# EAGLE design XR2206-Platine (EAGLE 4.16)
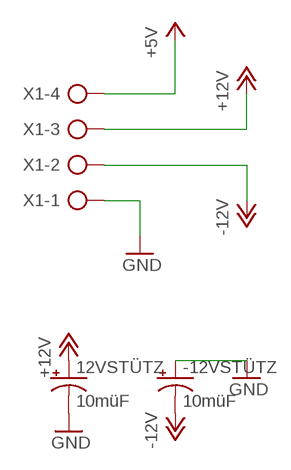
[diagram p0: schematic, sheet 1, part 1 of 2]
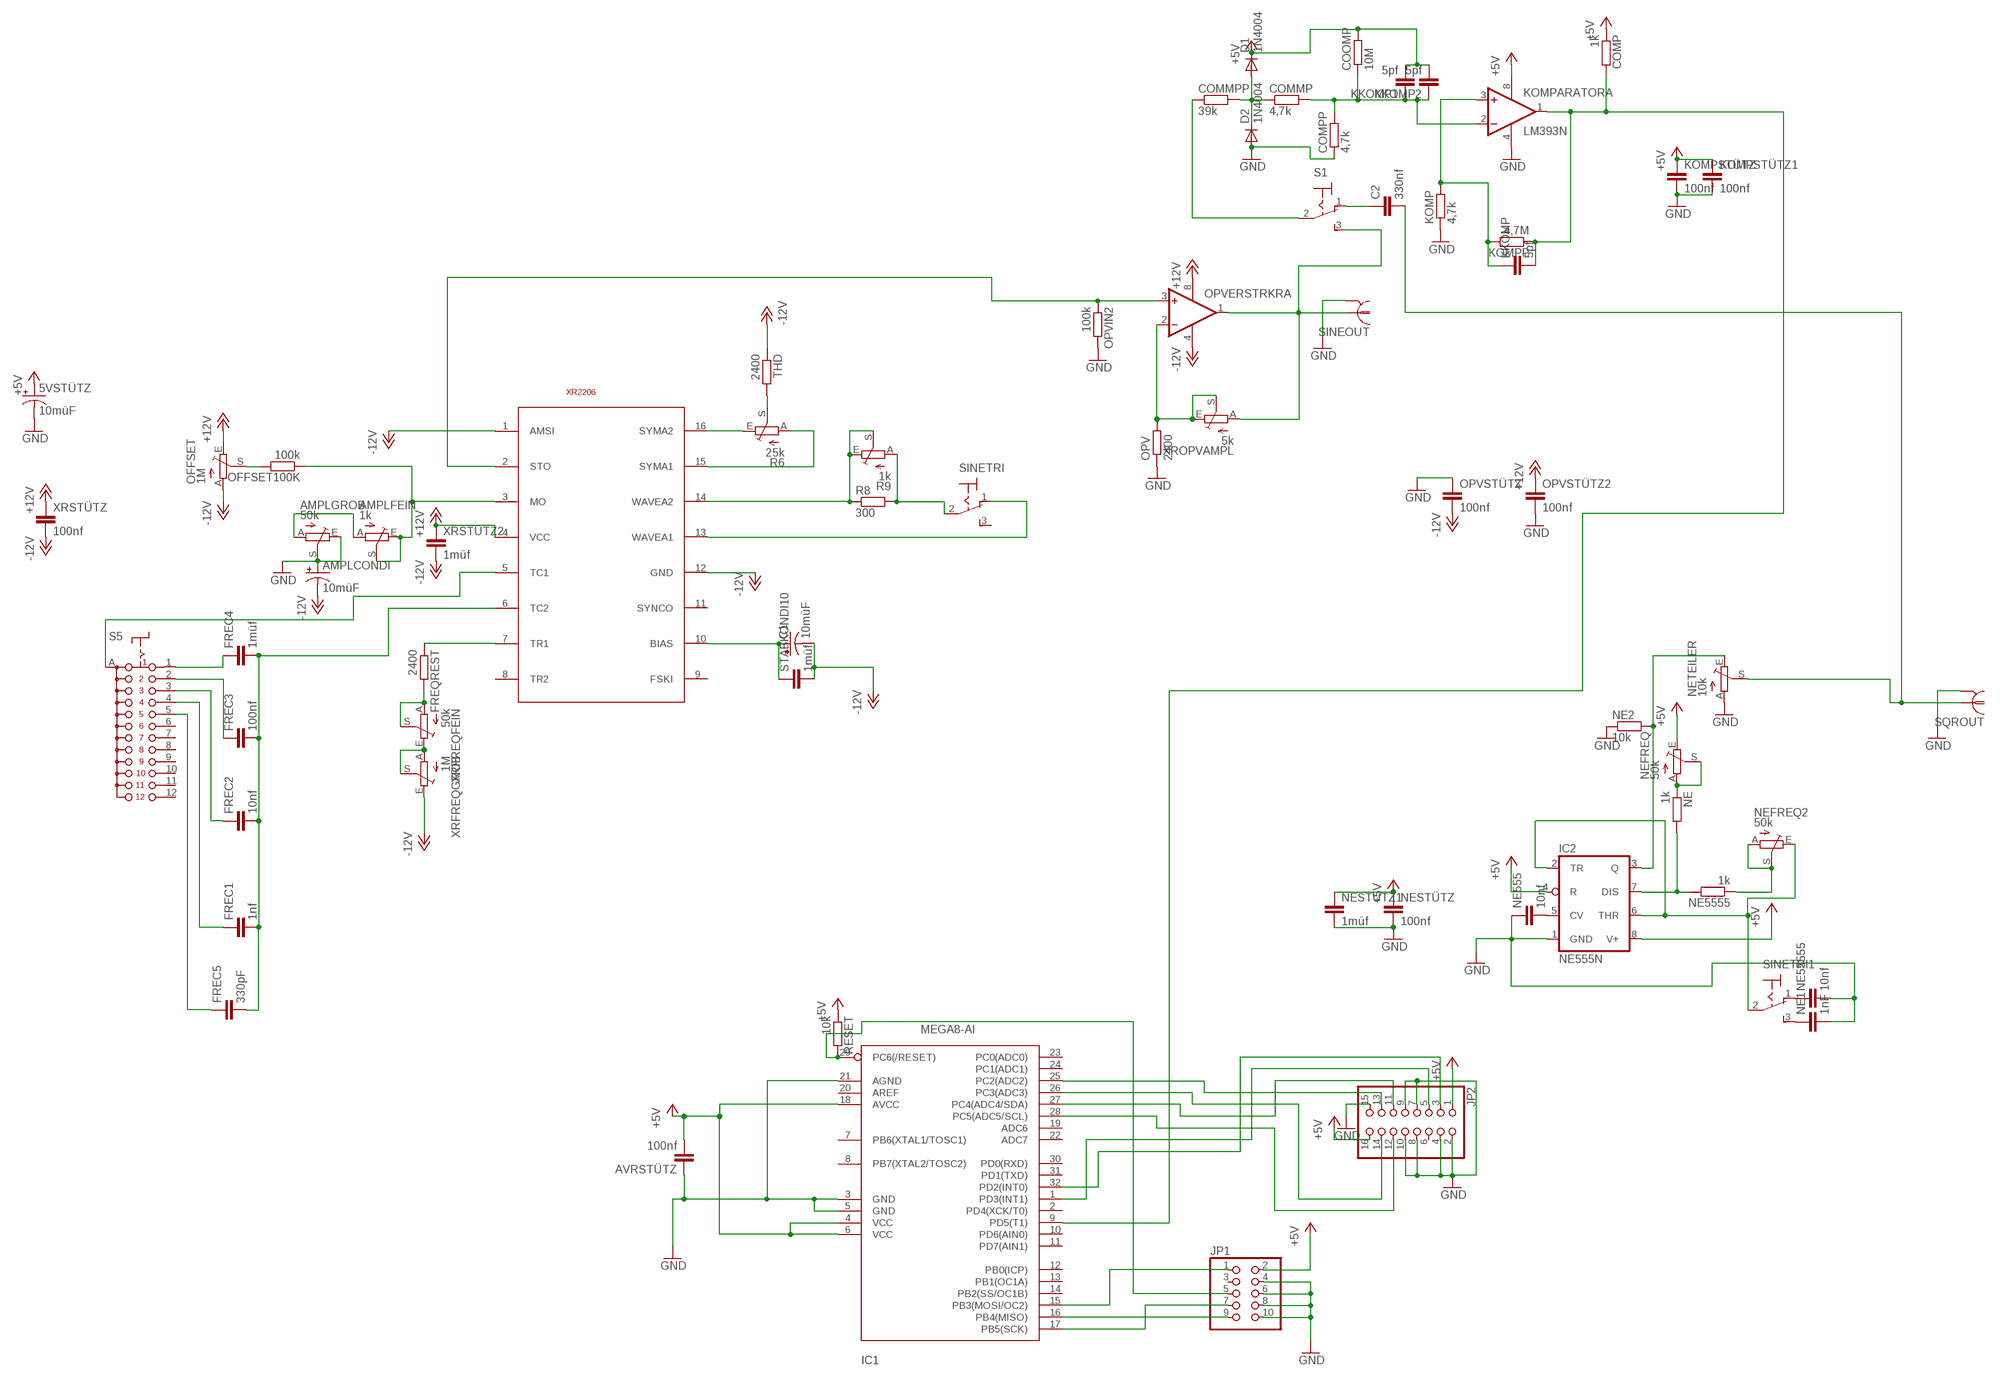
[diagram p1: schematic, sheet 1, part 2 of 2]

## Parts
5VSTÜTZ  10müF  CPOL-USE2.5-5  [E2,5-5]
12VSTÜTZ  10müF  CPOL-USE2.5-5  [E2,5-5]
-12VSTÜTZ  10müF  CPOL-USE2.5-5  [E2,5-5]
AMPLCONDI  10müF  CPOL-USE2.5-5  [E2,5-5]
AMPLFEIN  1k  TRIM_EU-LI10  [LI10]
AMPLGROB  50k  TRIM_EU-LI10  [LI10]
AVRSTÜTZ  100nf  C-EUC0603  [C0603]
C1  10müF  CPOL-USE2.5-5  [E2,5-5]
C2  330nf  C-EU050-025X075  [C050-025X075]
COMMP  4,7k  R-EU_R0603  [R0603]
COMMPP  39k  R-EU_R0603  [R0603]
COMP  1k  R-EU_R0603  [R0603]
COMPP  4,7k  R-EU_R0603  [R0603]
COOMP  10M  R-EU_R0603  [R0603]
D1  1N4004  [DO41-10]
D2  1N4004  [DO41-10]
FREC1  1nf  C-EUC0603  [C0603]
FREC2  10nf  C-EUC0603  [C0603]
FREC3  100nf  C-EUC0603  [C0603]
FREC4  1müf  C-EUC0603  [C0603]
FREC5  330pF  C-EUC0603  [C0603]
FREQREST  2400  R-EU_R0603  [R0603]
IC1  MEGA8-AI  [TQFP32-08]
IC2  NE555N  [DIL08]
JP1  PINHD-2X5  [2X05]
JP2  PINHD-2X8  [2X08]
KKOMP  5pf  C-EUC0603  [C0603]
KKOMP1  5pf  C-EUC0603  [C0603]
KKOMP2  5pf  C-EUC0603  [C0603]
KOMP  4,7k  R-EU_R0603  [R0603]
KOMPARATOR  LM393N  [DIL08]
KOMPP  4,7M  R-EU_R0603  [R0603]
KOMPSTÜTZ  100nf  C-EUC0603  [C0603]
KOMPSTÜTZ1  100nf  C-EUC0603  [C0603]
NE  1k  R-EU_R0603  [R0603]
NE1  1nF  C-EUC0603  [C0603]
NE2  10k  R-EU_R0603  [R0603]
NE555  10nf  C-EUC0603  [C0603]
NE5555  1k  R-EU_R0603  [R0603]
NE55555  10nf  C-EUC0603  [C0603]
NEFREQ  50k  TRIM_EU-LI10  [LI10]
NEFREQ2  50k  TRIM_EU-LI10  [LI10]
NESTÜTZ  100nf  C-EUC0603  [C0603]
NESTÜTZ1  1müf  C-EUC0603  [C0603]
NETEILER  10k  TRIM_EU-LI10  [LI10]
OFFSET  1M  TRIM_EU-LI10  [LI10]
OFFSET100K  100k  R-EU_R0603  [R0603]
OPV  2400  R-EU_R0603  [R0603]
OPVERSTRKR  2AMP_P8+4N  [DIL08]
OPVIN2  100k  R-EU_R0603  [R0603]
OPVSTÜTZ  100nf  C-EUC0603  [C0603]
OPVSTÜTZ2  100nf  C-EUC0603  [C0603]
R6  25k  TRIM_EU-LI10  [LI10]
R8  300  R-EU_R0603  [R0603]
R9  1k  TRIM_EU-LI10  [LI10]
RESET  10k  R-EU_R0603  [R0603]
S1  320-916  [320-916]
S5  CK101X12  [CK101X12]
SINEOUT  R141426  [R141426]
SINETRI  320-916  [320-916]
SINETRI1  320-916  [320-916]
SQROUT  R141426  [R141426]
STABKONDI10  1müf  C-EUC0603  [C0603]
THD  2400  R-EU_R0603  [R0603]
U$1  XR2206  [DIL16]
X1  AK300/4  [AK300/4]
XRFREQFEIN  50k  TRIM_EU-LI10  [LI10]
XRFREQGROB  1M  TRIM_EU-LI10  [LI10]
XROPVAMPL  5k  TRIM_EU-LI10  [LI10]
XRSTÜTZ  100nf  C-EUC0603  [C0603]
XRSTÜTZ2  1müf  C-EUC0603  [C0603]

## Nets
+5V: 5VSTÜTZ.+ AVRSTÜTZ.2 COMP.1 COOMP.2 D1.C IC1.4(VCC) IC1.6(VCC) IC1.18(AVCC) IC2.4(R) IC2.8(V+) JP1.2 JP2.1 JP2.16 KKOMP1.2 KKOMP2.2 KOMPARATOR.8(P:V+) KOMPSTÜTZ1.1 KOMPSTÜTZ.1 NEFREQ.E NESTÜTZ1.1 NESTÜTZ.1 RESET.1 X1.4
+12V: 12VSTÜTZ.+ OFFSET.E OPVERSTRKR.8(P:V+) OPVSTÜTZ2.1 U$1.4(VCC) X1.3 XRSTÜTZ2.1 XRSTÜTZ.1
-12V: -12VSTÜTZ.- AMPLCONDI.- C1.- OFFSET.A OPVERSTRKR.4(P:V-) OPVSTÜTZ.2 STABKONDI10.2 THD.1 U$1.1(AMSI) U$1.12(GND) X1.2 XRFREQGROB.E XRSTÜTZ2.2 XRSTÜTZ.2
GND: 5VSTÜTZ.- 12VSTÜTZ.- -12VSTÜTZ.+ AMPLCONDI.+ AMPLGROB.E AMPLGROB.S AVRSTÜTZ.1 COMPP.1 D2.A IC1.3(GND) IC1.5(GND) IC1.21(AGND) IC2.1(GND) JP1.4 JP1.6 JP1.8 JP1.10 JP2.2 JP2.4 JP2.7 JP2.8 JP2.9 JP2.10 JP2.15 KOMP.1 KOMPARATOR.4(P:V-) KOMPSTÜTZ1.2 KOMPSTÜTZ.2 NE1.2 NE2.1 NE555.1 NE55555.2 NESTÜTZ1.2 NESTÜTZ.2 NETEILER.A OPV.1 OPVIN2.2 OPVSTÜTZ2.2 OPVSTÜTZ.1 SINEOUT.2(GND) SQROUT.2(GND) X1.1
N$1: IC1.17(PB5(SCK)) JP1.7
N$2: IC2.7(DIS) NE5555.2 NE.2
N$3: FREQREST.1 U$1.7(TR1)
N$4: OFFSET100K.2 OFFSET.S
N$5: NE.1 NEFREQ.A NEFREQ.S
N$6: SINETRI.1(O) U$1.13(WAVEA1)
N$7: R6.E U$1.16(SYMA2)
N$8: R6.A U$1.15(SYMA1)
N$9: R6.S THD.2
N$10: R8.1 R9.E R9.S U$1.14(WAVEA2)
N$11: IC2.5(CV) NE555.2
N$12: R8.2 R9.A SINETRI.2(P)
N$13: S5.A U$1.5(TC1)
N$14: FREC4.1 S5.1
N$15: FREC3.1 S5.2
N$16: FREC2.1 S5.3
N$17: FREC1.1 S5.4
N$18: FREC1.2 FREC2.2 FREC3.2 FREC4.2 FREC5.2 U$1.6(TC2)
N$19: C1.+ STABKONDI10.1 U$1.10(BIAS)
N$20: OPVERSTRKR.3(A:+IN) OPVIN2.1 U$1.2(STO)
N$21: IC1.16(PB4(MISO)) JP1.9
N$22: OPV.2 OPVERSTRKR.2(A:-IN) XROPVAMPL.E XROPVAMPL.S
N$23: OPVERSTRKR.1(A:OUT) S1.3(S) SINEOUT.1 XROPVAMPL.A
N$24: AMPLFEIN.E AMPLFEIN.S OFFSET100K.1 U$1.3(MO)
N$25: IC2.2(TR) IC2.6(THR) NEFREQ2.E SINETRI1.2(P)
N$26: IC2.3(Q) NE2.2 NETEILER.E
N$27: AMPLFEIN.A AMPLGROB.A
N$28: NE5555.1 NEFREQ2.A NEFREQ2.S
N$29: FREQREST.2 XRFREQFEIN.A XRFREQFEIN.S
N$30: C2.1 S1.1(O)
N$31: IC1.29(PC6(/RESET)) JP1.5 RESET.2
N$32: COMP.2 IC1.9(PD5(T1)) KKOMP.2 KOMPARATOR.1(A:OUT) KOMPP.1
N$33: COMMP.1 COMMPP.2 D1.A D2.C
N$34: COMMP.2 COMPP.2 COOMP.1 KKOMP1.1 KKOMP2.1 KOMPARATOR.2(A:-IN)
N$35: FREC5.1 S5.5
N$36: KKOMP.1 KOMP.2 KOMPARATOR.3(A:+IN) KOMPP.2
N$37: XRFREQFEIN.E XRFREQGROB.A XRFREQGROB.S
N$38: IC1.15(PB3(MOSI/OC2)) JP1.1
N$40: COMMPP.1 S1.2(P)
N$41: NE55555.1 SINETRI1.1(O)
N$42: NE1.1 SINETRI1.3(S)
N$43: IC1.32(PD2(INT0)) JP2.3
N$44: IC1.1(PD3(INT1)) JP2.5
N$45: IC1.28(PC5(ADC5/SCL)) JP2.12
N$46: IC1.27(PC4(ADC4/SDA)) JP2.11
N$47: IC1.26(PC3(ADC3)) JP2.14
N$49: IC1.25(PC2(ADC2)) JP2.13
NEKOMP: C2.2 NETEILER.S SQROUT.1
Unconnected: IC1.2(PD4(XCK/T0)) IC1.7(PB6(XTAL1/TOSC1)) IC1.8(PB7(XTAL2/TOSC2)) IC1.10(PD6(AIN0)) IC1.11(PD7(AIN1)) IC1.12(PB0(ICP)) IC1.13(PB1(OC1A)) IC1.14(PB2(SS/OC1B)) IC1.19(ADC6) IC1.20(AREF) IC1.22(ADC7) IC1.23(PC0(ADC0)) IC1.24(PC1(ADC1)) IC1.30(PD0(RXD)) IC1.31(PD1(TXD)) JP1.3 JP2.6 KOMPARATOR.5(B:+IN) KOMPARATOR.6(B:-IN) KOMPARATOR.7(B:OUT) OPVERSTRKR.5(B:+IN) OPVERSTRKR.6(B:-IN) OPVERSTRKR.7(B:OUT) S5.6 S5.7 S5.8 S5.9 S5.10 S5.11 S5.12 SINETRI.3(S) U$1.8(TR2) U$1.9(FSKI) U$1.11(SYNCO)

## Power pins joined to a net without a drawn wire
GND: SINEOUT.3(GND) SINEOUT.4(GND) SINEOUT.5(GND) SQROUT.3(GND) SQROUT.4(GND) SQROUT.5(GND)

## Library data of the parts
5VSTÜTZ 12VSTÜTZ -12VSTÜTZ AMPLCONDI C1 = rcl:CPOL-US: POLARIZED CAPACITOR, American symbol
AMPLFEIN AMPLGROB NEFREQ NEFREQ2 NETEILER OFFSET R6 R9 XRFREQFEIN XRFREQGROB XROPVAMPL = pot:TRIM_EU-: POTENTIOMETER
AVRSTÜTZ C2 FREC1-FREC5 KKOMP KKOMP1 KKOMP2 KOMPSTÜTZ KOMPSTÜTZ1 NE1 NE555 NE55555 NESTÜTZ NESTÜTZ1 OPVSTÜTZ OPVSTÜTZ2 STABKONDI10 XRSTÜTZ XRSTÜTZ2 = rcl:C-EU: CAPACITOR, European symbol
COMMP COMMPP COMP COMPP COOMP FREQREST KOMP KOMPP NE NE2 NE5555 OFFSET100K OPV OPVIN2 R8 RESET THD = rcl:R-EU_: RESISTOR, European symbol
D1 D2 = diode:1N4004: DIODE
IC1 = atmel:MEGA8: MICROCONTROLLER 8 Kbytes FLASH 1 kbytes SRAM 512 bytes EEPROM USART 6-channel 10 bit ADC 2-channel 8 bit ADC Source: avr.lbr
IC2 = linear:*555: TIMER
JP1 = pinhead:PINHD-2X5: PIN HEADER
JP2 = pinhead:PINHD-2X8: PIN HEADER
KOMPARATOR = linear:LM393: COMPARATOR
OPVERSTRKR = linear:2AMP_P8+4: OP AMP
S1 SINETRI SINETRI1 = switch:320-916: TOGGLE SWITCH distributor RS Components
S5 = switch:CK101X12: ROTARY SWITCH C&K
SINEOUT SQROUT = con-coax:R141426: BNC COAX CONNECTOR Radiall 50/75 Ohm Spoerle
U$1 = linear:XR2206
X1 = con-ptr500:AK300/4: CONNECTOR

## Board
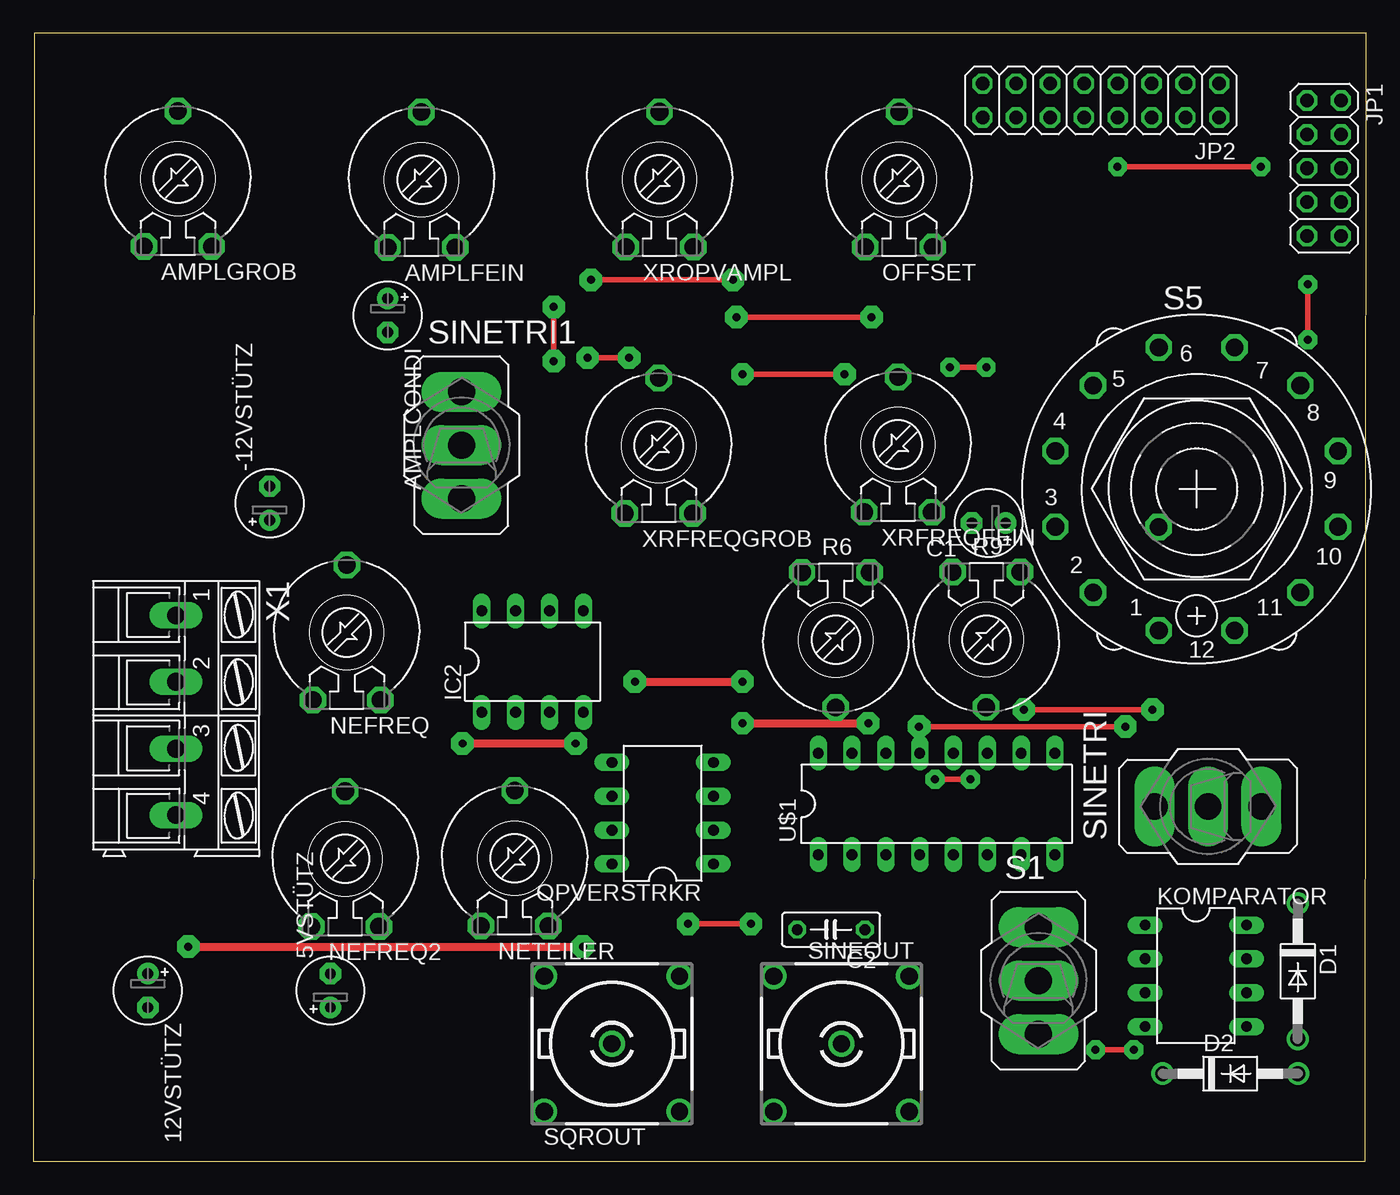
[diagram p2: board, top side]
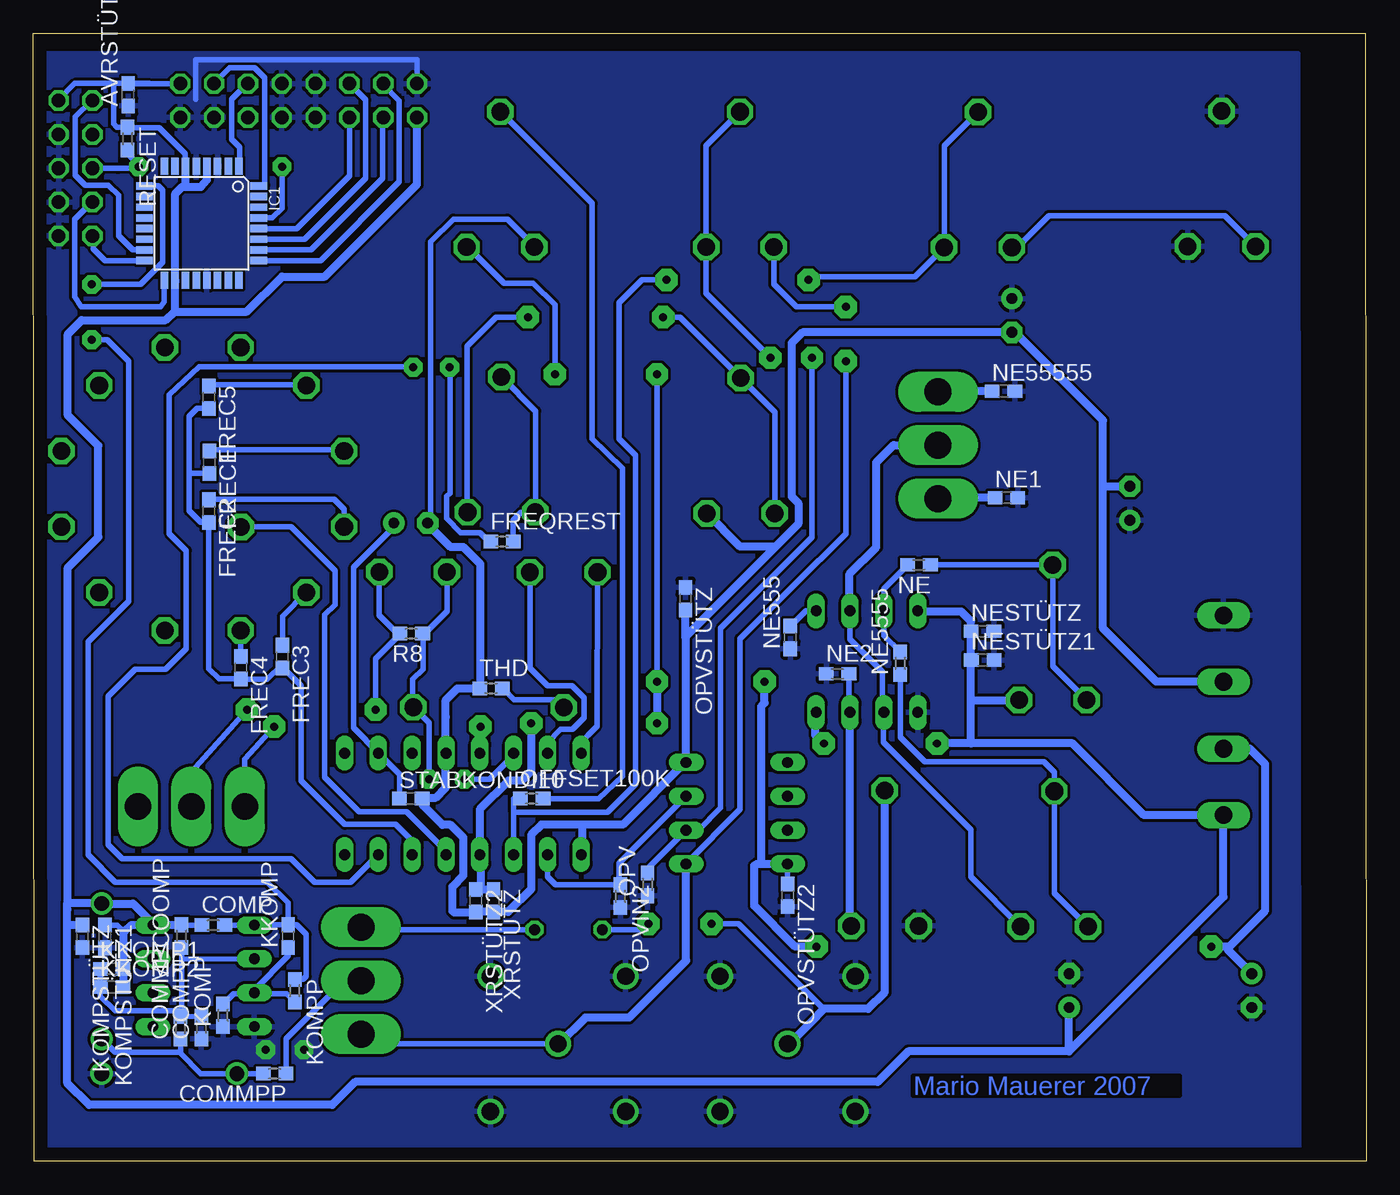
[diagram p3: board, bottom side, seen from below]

Size 100.09 x 84.67 mm. Coordinates in mm from the lower left corner, seen from the top.
Outline: 0,0 100,0 100.09,84.67 0.09,84.67 0,0
Copper layers (1*16): Top 0.035mm / dielectric 1.5mm / Bottom 0.035mm
Design rules "default": minimum track width 10mil, minimum drill 24mil, track to track 8mil, track to pad 8mil, pad to pad 8mil, via to via 8mil, smd to smd 8mil, copper to edge 40mil, drill to drill 8mil, minimum pad ring 10mil, minimum via ring 8mil, stop-mask expansion 4mil, vias tented up to drill 0mil, thermal gap 10mil

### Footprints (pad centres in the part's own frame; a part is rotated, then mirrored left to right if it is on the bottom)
E2,5-5 = drill 0.813 pad 1.6 round: + -1.27,0 | drill 0.813 pad 1.6 octagon: - 1.27,0
LI10 = drill 1.321 octagon: A -2.54,-5.08; E 2.54,-5.08; S 0,5.08
C0603 = smd 1.1 x 1: 1 -0.85,0; 2 0.85,0
C050-025X075 = drill 0.813 octagon: 1 -2.54,0; 2 2.54,0
R0603 = smd 1.1 x 1: 1 -0.85,0; 2 0.85,0
DO41-10 = drill 1.118 round: A 5.08,0; C -5.08,0
TQFP32-08 = smd 1.27 x 0.559: 1 -4.293,2.8; 2 -4.293,2; 3 -4.293,1.2; 4 -4.293,0.4; 5 -4.293,-0.4; 6 -4.293,-1.2; 7 -4.293,-2; 8 -4.293,-2.8; 17 4.293,-2.8; 18 4.293,-2; 19 4.293,-1.2; 20 4.293,-0.4; 21 4.293,0.4; 22 4.293,1.2; 23 4.293,2; 24 4.293,2.8 | smd 0.559 x 1.27: 9 -2.8,-4.293; 10 -2,-4.293; 11 -1.2,-4.293; 12 -0.4,-4.293; 13 0.4,-4.293; 14 1.2,-4.293; 15 2,-4.293; 16 2.8,-4.293; 25 2.8,4.293; 26 2,4.293; 27 1.2,4.293; 28 0.4,4.293; 29 -0.4,4.293; 30 -1.2,4.293; 31 -2,4.293; 32 -2.8,4.293
DIL08 = drill 0.813 long: 1 -3.81,-3.81; 2 -1.27,-3.81; 3 1.27,-3.81; 4 3.81,-3.81; 5 3.81,3.81; 6 1.27,3.81; 7 -1.27,3.81; 8 -3.81,3.81
2X05 = drill 1.016 octagon: 1 -5.08,-1.27; 2 -5.08,1.27; 3 -2.54,-1.27; 4 -2.54,1.27; 5 0,-1.27; 6 0,1.27; 7 2.54,-1.27; 8 2.54,1.27; 9 5.08,-1.27; 10 5.08,1.27
2X08 = drill 1.016 octagon: 1 -8.89,-1.27; 2 -8.89,1.27; 3 -6.35,-1.27; 4 -6.35,1.27; 5 -3.81,-1.27; 6 -3.81,1.27; 7 -1.27,-1.27; 8 -1.27,1.27; 9 1.27,-1.27; 10 1.27,1.27; 11 3.81,-1.27; 12 3.81,1.27; 13 6.35,-1.27; 14 6.35,1.27; 15 8.89,-1.27; 16 8.89,1.27
320-916 = drill 2.007 long: 1 0,4.013; 2 0,0; 3 0,-4.013
CK101X12 = drill 1.321 octagon: 1 -2.845,-10.617; 2 -7.772,-7.772; 3 -10.617,-2.845; 4 -10.617,2.845; 5 -7.772,7.772; 6 -2.845,10.617; 7 2.845,10.617; 8 7.772,7.772; 9 10.617,2.845; 10 10.617,-2.845; 11 7.772,-7.772; 12 2.845,-10.617; A -2.87,-2.87
R141426 = drill 1.295 round: 1 0,0; 2 5.08,5.08; 3 -5.08,5.08; 4 -5.08,-5.08; 5 5.08,-5.08
DIL16 = drill 0.813 long: 1 -8.89,-3.81; 2 -6.35,-3.81; 3 -3.81,-3.81; 4 -1.27,-3.81; 5 1.27,-3.81; 6 3.81,-3.81; 7 6.35,-3.81; 8 8.89,-3.81; 9 8.89,3.81; 10 6.35,3.81; 11 3.81,3.81; 12 1.27,3.81; 13 -1.27,3.81; 14 -3.81,3.81; 15 -6.35,3.81; 16 -8.89,3.81
AK300/4 = drill 1.321 long: 1 -7.493,0; 2 -2.515,0; 3 2.515,0; 4 7.493,0

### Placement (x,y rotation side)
5VSTÜTZ  22.31,12.82 90 top
12VSTÜTZ  8.6,12.82 270 top
-12VSTÜTZ  17.74,49.4 90 top
AMPLCONDI  26.61,63.5 270 top
AMPLFEIN  29.15,73.68 0 top
AMPLGROB  10.86,73.76 0 top
AVRSTÜTZ  92.96,80.07 90 bottom
C1  71.74,47.91 180 top
C2  59.91,17.39 180 top
COMMP  89.04,10.04 90 bottom
COMMPP  81.97,6.59 180 bottom
COMP  86.56,17.74 0 bottom
COMPP  87.47,10.05 90 bottom
COOMP  88.96,16.91 90 bottom
D1  94.95,14.27 270 top
D2  89.88,6.59 0 top
FREC1  86.87,52.47 270 bottom
FREC2  86.91,48.81 270 bottom
FREC3  81.38,37.89 270 bottom
FREC4  84.51,37.05 270 bottom
FREC5  86.91,57.36 270 bottom
FREQREST  64.88,46.52 0 bottom
IC1  87.45,70.42 270 bottom
IC2  37.49,37.51 0 top
JP1  96.91,74.54 270 top
JP2  80.16,79.62 180 top
KKOMP  80.95,16.91 90 bottom
KKOMP1  94.2,14.45 0 bottom
KKOMP2  94.2,13.08 0 bottom
KOMP  85.84,10.97 90 bottom
KOMPARATOR  87.3,13.93 270 top
KOMPP  80.45,12.81 270 bottom
KOMPSTÜTZ  96.41,16.9 270 bottom
KOMPSTÜTZ1  94.7,16.89 270 bottom
NE  33.58,44.78 180 bottom
NE1  27.01,49.8 0 bottom
NE2  39.69,36.6 0 bottom
NE555  43.24,39.33 90 bottom
NE5555  34.99,37.38 90 bottom
NE55555  27.23,57.81 0 bottom
NEFREQ  23.53,39.7 0 top
NEFREQ2  23.42,22.7 0 top
NESTÜTZ  28.8,39.78 0 bottom
NESTÜTZ1  28.79,37.63 0 bottom
NETEILER  36.14,22.75 0 top
OFFSET  65.01,73.71 0 top
OFFSET100K  62.66,27.22 0 bottom
OPV  53.96,20.78 90 bottom
OPVERSTRKR  47.26,26.13 90 top
OPVIN2  56.01,19.91 270 bottom
OPVSTÜTZ  51.12,42.24 270 bottom
OPVSTÜTZ2  43.45,19.97 270 bottom
R6  60.26,39.14 180 top
R8  71.7,39.62 180 bottom
R9  71.56,39.16 180 top
RESET  93.01,76.77 270 bottom
S1  75.48,13.56 0 top
S5  87.36,50.48 0 top
SINEOUT  60.68,8.82 0 top
SINETRI  88.21,26.64 90 top
SINETRI1  32.16,53.75 0 top
SQROUT  43.45,8.82 180 top
STABKONDI10  71.74,27.22 0 bottom
THD  65.71,35.5 0 bottom
U$1  67.83,26.83 0 top
X1  10.72,33.48 270 top
XRFREQFEIN  64.94,53.8 0 top
XRFREQGROB  46.96,53.72 0 top
XROPVAMPL  47.02,73.71 0 top
XRSTÜTZ  65.53,19.57 270 bottom
XRSTÜTZ2  66.87,19.57 270 bottom

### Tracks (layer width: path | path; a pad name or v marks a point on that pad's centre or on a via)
+5V  (via drill 0.6 pad 1.68)
  Top 0.61: v32.22,31.36 v40.73,31.36
  Bottom 0.406: JP1.2 98.21,79.61 | 98.21,79.61 98.22,79.61 | 98.21,79.61 98.21,79.62 JP1.2 | JP2.1 88.95,80.89 88.95,80.83 89.01,80.89 92.94,80.89 AVRSTÜTZ.2 | IC1.4 | IC1.6 88.67,75.62 90.64,77.59 92.93,77.59 | X1.4 10.72,26.03 | 29.68,37.62 NESTÜTZ1.1 | 29.68,39.78 NESTÜTZ.1 | 33.74,41.27 33.68,41.27 IC2.8 | 97.54,18.92 97.54,18.89 97.52,18.89 | COOMP.2 88.91,17.72 88.9,17.74 COMP.1 | 91.14,17.76 91.15,17.75 91.14,17.74 KOMPARATOR.8 91.11,17.86 | 94.96,19.43 94.96,19.36 D1.C | 97.52,19.4 97.5,19.43 | 89.42,63.83 89.42,63.77 | 92.93,77.59 92.99,77.59 RESET.1 92.93,77.62 | JP1.2 98.26,79.62 96.97,80.92 AVRSTÜTZ.2 | AVRSTÜTZ.2 91.4,80.92 | AVRSTÜTZ.2 94.07,80.92 94.07,77.88 93.81,77.62 92.93,77.62 | 92.93,77.59 92.93,77.62 | 92.93,77.59 92.93,77.62 | 88.91,73.15 88.65,73.15 | 97.52,17.75 | 93.33,14.88 93.35,14.87 KKOMP1.2 | KKOMP2.2 93.35,13.34 93.33,13.36 93.35,13.37 | 93.18,17.14 93.26,17.22 93.78,17.74 KOMPSTÜTZ1.1 | 89.42,66.06 89.42,66.12 IC1.18 89.45,66.09 89.42,66.06
  Bottom 0.61: IC1.4 87.05,73.68 87.5,73.15 88.65,73.15 IC1.6 | 41.36,33.76 41.36,33.78 | 41.36,33.76 IC2.4 | v40.73,31.36 41.36,32 41.36,33.76 | 29.68,31.36 22.06,31.36 16.69,25.99 X1.4 10.72,19.84 22.31,8.25 | 29.68,31.36 v32.22,31.36 | 29.68,34.62 NEFREQ.E | 29.68,34.62 29.68,37.62 29.68,39.78 29.68,40.55 30.4,41.27 33.68,41.27 | 29.68,31.36 29.68,34.62 | 22.31,8.25 34.38,8.25 36.67,5.96 75.91,5.96 77.64,4.24 95.91,4.24 97.52,5.85 97.52,17.75 97.52,18.89 97.52,19.4 | 91.14,17.76 COOMP.2 | 94.96,19.36 D1.C | 94.96,19.43 97.5,19.43 97.5,44.57 95.21,46.86 95.21,53.72 97.5,56 97.5,62.1 96.46,63.14 90.16,63.14 89.42,63.83 89.42,66.06 | JP2.16 71.27,73.34 78.19,66.42 81.42,66.42 84.06,63.77 89.42,63.77 | 89.42,66.12 89.42,72.64 88.91,73.15 | 97.52,17.75 KOMPSTÜTZ.1 | D1.C 92.6,19.35 91.11,17.86 | 91.14,17.74 92.74,17.74 93.26,17.22 93.33,17.14 93.33,14.88 | KKOMP1.2 93.35,13.37 | 22.31,8.25 5VSTÜTZ.+
+12V  (via drill 0.6 pad 1.68)
  Top 0.406: v53.25,59.08 v60.92,59.08
  Top 0.61: v11.65,16.12 v41.26,16.12 | v45.17,36.01 v53.25,36.01 | v53.25,32.89 v62.7,32.89
  Bottom 0.406: XRSTÜTZ.1 66.51,20.42 | 66.51,23.02 U$1.4 66.56,23.01 66.51,22.96 | 8.74,30.97 X1.3 | 45.94,22.2 45.76,22.32 | 43.45,20.77 OPVSTÜTZ2.1 OPVERSTRKR.8 | v53.25,36.01 v53.25,59.08 | OFFSET.E 67.55,68.68 67.53,68.7 64.73,65.91 62.55,65.91 60.92,64.28 v60.92,59.08 | 66.76,20.44 66.76,20.42 XRSTÜTZ2.1 66.84,20.44 66.51,20.44
  Bottom 0.61: 8.74,30.97 7.58,29.81 7.58,18.82 10.28,16.12 10.38,16.12 | 10.38,16.12 v11.65,16.12 | v41.26,16.12 42.89,16.12 45.94,19.17 45.94,22.2 | 45.43,22.32 OPVERSTRKR.8 | 45.76,22.32 45.43,22.32 | v53.25,36.01 v53.25,32.89 | v62.7,32.89 62.7,29.29 63.42,28.57 64.4,28.57 66.56,26.41 U$1.4 | 66.76,20.42 XRSTÜTZ.1 | 66.51,22.96 66.51,20.44 | 12VSTÜTZ.+ 10.38,15.87 10.38,16.12 | 45.43,22.32 45.43,34.16 45.17,34.41 v45.17,36.01
-12V
  Bottom 0.406: 69.11,30.64 U$1.12 | 69.11,33.57 69.11,33.37 69.13,33.37 | 58.93,22.96 58.93,23.02 U$1.1 58.89,23.02 58.89,22.98 | XRSTÜTZ.2 66.55,18.64 | 70.28,47.63 70.28,47.66 C1.- 70.23,47.65 70.24,47.65 70.24,69.03 68.54,70.73 64.48,70.73 62.45,68.7 62.47,68.68 OFFSET.A | 51.12,29.94 51.14,29.94 51.14,29.97 51.12,29.97 51.12,31.96 | AMPLCONDI.- 26.34,62.23 26.34,62.24 | X1.2 10.72,35.85 | 66.51,35.43 66.51,35.45 THD.1 | 70.83,26.72 70.83,27.3 STABKONDI10.2 | 67.78,22.14 67.79,22.22
  Bottom 0.61: 69.11,33.37 69.11,30.64 69.11,28.04 69.86,27.3 70.83,27.3 | 67.79,22.22 67.79,24.3 68.75,25.25 69.37,25.25 70.83,26.72 | X1.2 15.77,36 19.77,40 19.77,50.67 | 19.77,50.67 19.77,55.62 26.38,62.23 | AMPLCONDI.- 42.33,62.23 43.14,61.41 43.14,49.91 42.63,49.4 42.63,47.85 44.36,46.12 | 44.36,46.12 51.12,39.37 | 44.36,46.12 44.39,46.15 47.02,46.15 XRFREQGROB.E | 51.12,39.37 OPVSTÜTZ.2 | OPVERSTRKR.4 51.12,29.94 51.12,39.37 | 51.14,29.94 55.82,25.27 58.89,25.27 | 58.89,25.27 58.89,23.02 | 58.89,25.27 61.94,25.27 62.7,24.51 62.7,20.44 64.43,18.72 XRSTÜTZ.2 XRSTÜTZ2.2 66.92,18.66 68.49,18.66 68.62,18.79 | THD.1 68.24,35.5 69.13,34.62 69.13,33.37 | 70.28,47.63 68.75,46.1 67.78,46.1 66.51,44.83 66.51,35.45 | 67.78,22.14 67.78,21.46 68.62,20.62 68.62,18.79 | 19.77,50.67 -12VSTÜTZ.- | 68.62,18.79
  Bottom 0.813: 26.38,62.23 AMPLCONDI.-
GND  (via drill 0.6 pad 1.42)
  Top 0.406: v79.77,8.38 v82.63,8.38
  Bottom 0.406: v82.63,8.38 82.63,8.3 | 87.88,79.73 87.88,82.67 71.27,82.67 JP2.15 71.27,80.86
  Bottom 0.813: 13.42,68.7 AMPLGROB.E 13.5,68.57 | AMPLCONDI.+ 26.63,64.79
  pour Bottom: 5.16,83.13 100.93,83.19 100.83,-0.13 5.05,-0.11
N$1
  Bottom 0.406: IC1.17 90.25,64.52 90.54,64.13 96.48,64.13 96.99,64.89 96.99,70.73 95.72,72 JP1.7
N$2
  Bottom 0.406: IC2.7 36.21,41.35 | IC2.7 36.22,41.26 36.23,41.25 36.23,41.32 | 36.23,41.32 36.23,41.35 | IC2.7 36.23,41.32 | 36.21,41.32 | IC2.7 36.21,41.31 36.21,39.45 NE5555.2 | IC2.7 36.21,41.32 | NE.2 36.21,43 36.21,41.32
N$3  (via drill 0.6 pad 1.42)
  Top 0.406: v71.55,59.61 v68.83,59.61
  Bottom 0.406: FREQREST.1 65.86,46.52 66.55,47.2 68,47.2 69.05,48.26 69.05,49.91 68.8,50.16 68.8,59.57 v68.83,59.61 | U$1.7 76.25,20.95 78.96,20.95 80.73,22.73 93.4,22.73 94.45,23.77 94.45,34.92 92.42,36.95 90.13,36.95 88.61,38.48 88.61,45.84 89.88,47.11 89.88,57.53 87.64,59.66 71.59,59.66 71.56,59.6 v71.55,59.61
N$4
  Bottom 0.406: OFFSET100K.2 61.61,27.2 57.66,27.2 55.84,28.91 55.84,52.01 58.13,54.22 58.13,71.9 OFFSET.S 64.99,78.91
N$5
  Bottom 0.406: NE.1 NEFREQ.S 23.53,37.16 NEFREQ.A
N$6  (via drill 0.6 pad 1.68)
  Top 0.406: v66.51,32.63 v82,32.63
  Bottom 0.406: SINETRI.1 84.2,30.18 v82,32.63 | 66.51,30.64 66.51,30.6 | U$1.13 66.51,30.64 | 66.51,30.64 v66.51,32.63
N$7
  Bottom 0.406: 58.94,30.66 58.98,30.66 | U$1.16 58.94,30.66 | R6.E 57.76,32.66 58.45,31.99 58.9,31.53 58.9,30.66 58.94,30.66
N$8
  Bottom 0.406: R6.A 62.8,37.02 61.49,35.71 59.65,35.71 58.73,34.78 58.73,33.32 59.61,32.43 60.51,32.43 61.48,31.43 U$1.15
N$9
  Bottom 0.406: R6.S 60.87,34.67 63.97,34.67 64.81,35.5 THD.2
N$10  (via drill 0.6 pad 1.42)
  Top 0.406: v67.72,28.68 v70.37,28.68
  Bottom 0.406: 70.83,39.89 70.83,39.87 R8.1 | 67.72,28.63 v67.72,28.68 67.72,28.66 | 64.06,30.64 64.06,30.65 | U$1.14 64.06,30.64 | 64.06,30.64 64.06,30.44 65.82,28.67 67.7,28.67 67.72,28.66 | 67.72,28.66 67.73,28.65 | 71.56,34.13 71.59,34.16 71.59,36.19 70.83,36.95 70.83,39.49 | 71.56,34.13 R9.S | v70.37,28.68 70.37,32.94 71.56,34.13 | R8.1 70.85,39.72 70.83,39.75 70.83,39.49 | 70.83,39.49 70.85,39.52 R8.1 | R9.E 69.03,41.3 70.83,39.49
N$11
  Bottom 0.406: NE555.2 43.22,40.18 42.07,41.32 IC2.5
N$12  (via drill 0.6 pad 1.68)
  Top 0.406: v74.38,33.9 v84.04,33.9
  Bottom 0.406: R9.A 74.11,40.99 72.61,39.49 | SINETRI.2 88.21,29.22 v84.04,33.9 | 72.61,39.49 72.55,39.54 R8.2 | v74.38,33.9 74.38,37.71 72.61,39.49
N$13
  Bottom 0.406: U$1.5 69.1,23.29 72.07,26.23 75.63,26.23 78.19,28.82 78.19,41.02 77.43,41.78 77.43,44.32 80.73,47.62 84.51,47.62 | 84.51,47.62 84.54,47.62 | 84.51,47.62 S5.A
N$14
  Bottom 0.406: FREC4.1 84.52,37.92 S5.1
N$15
  Bottom 0.406: FREC3.1 81.37,40.93 S5.2
N$16
  Bottom 0.406: FREC2.1 86.91,49.72 77.5,49.72 76.75,48.96 S5.3
N$17
  Bottom 0.406: FREC1.1 86.87,53.4 76.75,53.4 S5.4
N$18
  Bottom 0.406: 88.39,51.6 88.39,48.83 87.53,47.96 FREC2.2 86.91,36.97 86.15,36.22 84.51,36.22 | 88.39,51.6 88.39,51.63 86.93,51.63 86.93,51.62 FREC1.2 | 88.39,51.6 88.37,51.6 88.37,55.93 87.79,56.51 FREC5.2 | U$1.6 71.64,24.05 72.89,25.29 76.69,25.29 79.97,28.57 79.97,35.68 81.38,37.09 | 81.38,37.09 81.5,37.21 82.51,36.19 FREC4.2 | 81.38,37.09 FREC3.2 | FREC4.2 84.54,36.19 | FREC4.2 84.51,36.22 | 84.51,36.22 84.49,36.22
N$19
  Bottom 0.406: 74.14,30.64 74.13,30.64 | C1.+ 72.97,47.66 76.03,44.6 76.03,32.53 74.14,30.64 | 74.14,30.64 U$1.10 74.17,30.64 72.59,29.06 STABKONDI10.1
N$20
  Bottom 0.406: U$1.2 61.47,23.02 | OPVERSTRKR.3 56.1,22.37 56.1,20.7 56.07,20.7 OPVIN2.1 60.89,20.76 61.48,21.35 U$1.2 | U$1.2 61.48,23.03
N$21
  Bottom 0.406: JP1.9 95.61,69.46 95.61,68.51 94.7,67.61 91.78,67.61 91.78,67.62 IC1.16
N$22  (via drill 0.6 pad 1.68)
  Top 0.406: v41.62,60.32 v44.74,60.32
  Bottom 0.406: v41.62,60.32 41.62,46.86 48.48,40 48.48,26.54 50.15,24.86 OPVERSTRKR.2 53.96,21.97 OPV.2 53.96,21.58 | v44.74,60.32 49.59,65.17 49.59,68.63 | 49.59,68.63 49.59,68.68 49.56,68.65 XROPVAMPL.E 49.59,68.63 | XROPVAMPL.S 49.59,76.22 49.59,68.63
N$23  (via drill 0.6 pad 1.68)
  Top 0.406: v39.08,60.07 v39.08,64.13
  Bottom 0.406: OPVERSTRKR.1 47.03,26.44 47.03,39.24 39.08,47.11 v39.08,60.07 | v39.08,64.13 42.79,64.13 44.49,65.83 44.49,68.68 | 60.67,8.76 60.68,8.77 SINEOUT.1 74.7,8.82 75.42,9.54 S1.3
  Bottom 0.61: 44.49,68.68 44.48,68.67 XROPVAMPL.A | OPVERSTRKR.1 51.07,15.07 55.34,10.79 58.64,10.79 60.67,8.76
N$24  (via drill 0.6 pad 1.68)
  Top 0.406: v52.54,66.16 v41.87,66.16
  Bottom 0.406: AMPLFEIN.S 31.69,76.22 AMPLFEIN.E 33.87,66.42 41.62,66.42 v41.87,66.16 | OFFSET100K.1 64.02,27.2 64.02,26.21 | 64.02,26.21 U$1.3 | v52.54,66.16 54.39,66.16 56.1,64.46 56.1,54.22 54.88,53.01 54.88,28.29 56.96,26.21 64.02,26.21
N$25
  Bottom 0.406: IC2.2 36.26,33.7 | IC2.2 36.31,33.62 36.31,36.75 38.75,39.19 38.75,41.27 38.76,41.28 IC2.6 | NEFREQ2.E 29.68,21.34 29.68,24.9 36.23,31.45 36.23,33.68 36.22,33.68 IC2.2
  Bottom 0.61: 38.75,41.32 IC2.6 38.8,41.28 | SINETRI1.2 35.5,53.75 36.79,52.46 36.79,46.1 38.8,44.09 38.8,41.28 | 38.8,41.28 38.8,41.22
N$26
  Bottom 0.406: IC2.3 38.77,33.7 38.82,33.65 38.84,33.66 NE2.2 | 38.8,17.67 38.82,17.65 | NETEILER.E 38.8,17.67 | 38.8,17.67 38.76,17.71
  Bottom 0.61: 38.76,17.71 IC2.3
N$27
  Bottom 0.406: AMPLGROB.A 10.63,70.99 23.84,70.99 26.12,68.7 26.63,68.7 26.63,68.63 AMPLFEIN.A
N$28
  Bottom 0.406: NE5555.1 34.99,31.84 33.14,29.99 24.21,29.99 23.43,29.22 23.43,27.86 23.42,27.86 NEFREQ2.S 23.42,20.12 20.92,17.62 NEFREQ2.A
N$29
  Bottom 0.406: FREQREST.2 64.05,46.52 64.05,48.13 63.45,48.73 XRFREQFEIN.A 62.38,48.74 62.37,48.74 62.37,56.32 XRFREQFEIN.S
N$30
  Bottom 0.406: S1.1 75.4,17.57 75.4,17.39 C2.1
N$31  (via drill 0.6 pad 1.42)
  Top 0.406: v81.42,74.67 v92.16,74.67
  Bottom 0.406: JP1.5 95.64,74.56 93.78,74.54 93.69,74.54 93.69,74.53 | 93.69,74.53 92.2,74.53 v92.16,74.67 92.16,74.8 93.18,75.81 93.08,75.92 RESET.2 | 93.69,74.53 93.74,74.53 | v81.42,74.67 81.39,74.67 81.39,71.56 82.14,70.82 IC1.29
N$32  (via drill 0.6 pad 1.42)
  Top 0.406: v95.71,61.67 v95.71,65.82
  Bottom 0.406: IC1.9 90.71,73.22 90.39,72.89 90.39,67.48 92.02,65.82 v95.71,65.82 | KKOMP.2 80.33,17.76 79.59,17.03 79.59,13.88 79.81,13.66 80.43,13.66 | 80.43,13.66 80.43,13.64 | KOMPP.1 80.43,13.66 | KKOMP.2 83.47,17.76 KOMPARATOR.1 85.72,17.74 | 85.72,17.74 COMP.2 | 85.72,17.74 85.81,17.65 | v95.71,61.67 94.53,61.67 92.93,60.07 92.93,42.03 95.97,38.98 95.97,23 93.93,20.95 82.51,20.95 80.96,19.4 80.96,17.93 80.95,17.91 KKOMP.2
N$33
  Bottom 0.406: COMMPP.2 84.76,6.59 84.77,6.57 84.78,6.59 D2.C 84.8,6.73 84.95,6.57 87.52,6.57 89.04,8.1 89.04,8.17 | 89.04,8.17 COMMP.1 | D1.A 93.93,8.17 89.04,8.17
N$34
  Bottom 0.406: KOMPARATOR.2 88.96,15.17 | 88.96,10.85 COMMP.2 89.04,11.22 89.12,11.3 93.94,11.3 95.05,12.4 KKOMP2.1 95.06,13.33 95.08,13.36 95.05,13.39 KKOMP1.1 | 88.96,10.85 COMPP.2 | 88.96,15.17 88.96,10.85 | 88.96,15.17 COOMP.1
N$35
  Bottom 0.406: 86.91,58.3 86.93,58.3 | 86.91,58.3 FREC5.1 | S5.5 79.59,58.3 86.91,58.3
N$36
  Bottom 0.406: KOMPARATOR.3 83.48,12.66 83.48,12.59 | KKOMP.1 80.95,15.43 83.48,12.9 83.48,12.59 | 85.81,11.81 85.66,11.96 | 83.48,12.59 83.48,12.64 KOMPARATOR.3 | 83.53,12.57 83.53,12.62 KOMPARATOR.3 | KOMPP.2 81.06,12.57 83.53,12.57 | 85.81,11.81 85.83,11.82 KOMP.2 | 83.53,12.57 85.05,12.57 85.81,11.81
N$37  (via drill 0.6 pad 1.68)
  Top 0.406: v52.79,63.37 v62.95,63.37
  Bottom 0.406: XRFREQFEIN.E 67.47,48.74 67.49,48.74 | XRFREQFEIN.E 67.55,48.73 | XRFREQGROB.A 44.41,56.24 XRFREQGROB.S 51.54,63.37 v52.79,63.37 | 67.53,48.67 67.53,48.64 | 67.53,48.67 XRFREQFEIN.E | v62.95,63.37 65.34,63.37 67.53,61.18 67.53,48.67
N$38
  Bottom 0.406: 95.62,79.62 95.62,79.61 | 95.62,79.62 JP1.1 95.72,79.62 96.94,78.41 96.94,74.04 96.18,73.27 94.45,73.27 93.69,72.51 93.69,69.46 92.64,68.42 IC1.15 | 95.62,79.62 95.62,79.64
N$40
  Bottom 0.406: S1.2 76.75,13.56 81.11,9.19 81.11,6.57 81.12,6.57 COMMPP.1
N$41
  Bottom 0.61: SINETRI1.1 32.2,57.8 NE55555.1
N$42
  Bottom 0.61: SINETRI1.3 32.16,49.79 32.17,49.8 NE1.1
N$43
  Bottom 0.406: 83.16,73.29 83.2,73.29 | IC1.32 83.16,73.29 | 83.16,73.29 82.72,73.29 82.72,81.35 83.45,82.09 85.36,82.09 86.58,80.89 JP2.3
N$44
  Bottom 0.406: IC1.1 84.61,74.71 84.61,76.13 85.2,76.73 85.2,79.73 84.04,80.89 JP2.5
N$45
  Bottom 0.406: 76.38,78.35 JP2.12 76.35,78.37 | IC1.28 80.31,70.02 76.34,73.98 JP2.12 76.35,78.37 | 76.35,78.37 76.36,78.38
N$46
  Bottom 0.406: 76.38,80.89 JP2.11 75.12,79.67 75.12,73.78 79.71,69.22 IC1.27
N$47
  Bottom 0.406: 73.79,78.37 73.79,78.35 JP2.14 | IC1.26 79.24,68.42 73.88,73.78 73.88,78.28 JP2.14 | JP2.14
N$49
  Bottom 0.406: 73.75,80.84 JP2.13 73.88,80.89 72.61,79.62 72.61,73.53 78.52,67.62 IC1.25
NEKOMP  (via drill 0.6 pad 1.68)
  Top 0.406: v49.16,17.83 v53.89,17.83
  Bottom 0.406: SQROUT.1 43.69,8.82 | SQROUT.1 43.54,8.57 | SQROUT.1 43.45,8.83 | 54.19,17.55 53.91,17.83 v53.89,17.83 54.32,17.39 C2.2 | 40.72,11.44 40.74,11.44 47.13,17.83 v49.16,17.83
  Bottom 0.61: SQROUT.1 43.4,8.76 41.72,10.41 40.72,11.44 37.4,11.44 36.14,12.7 NETEILER.S

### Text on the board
Bottom: Mario Mauerer 2007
